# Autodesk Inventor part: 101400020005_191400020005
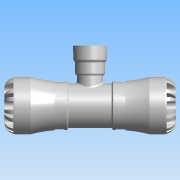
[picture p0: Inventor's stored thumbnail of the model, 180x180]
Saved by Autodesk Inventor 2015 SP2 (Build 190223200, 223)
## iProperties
Created: 2016-12
Part Number: 101400020005_191400020005
Material: PVC-Piping
Description: PLASSON TEE WITH THREADED FEMALE OFFTAKE 20X1/2" SERIES 1
Document SubType Name: Modeling
Designer: KIM
Mass: 664.223 g
Surface Area: 733.008 cm^2
Volume: 474.445 cm^3
Density: 1.4 g/cm^3
Appearance: Smooth - White
Author: KIM
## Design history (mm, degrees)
derived "1014.ipt"
feature "Solid1::1014.ipt"
tag "TaggingFeature1"
body "Solid1"
other parameters: "d1" = 18.9, "d3" = 25, "d4" = 41, "d8" = 34.85, "d13" = 6.4, "d14" = 6.4, "d15" = 0, "d17" = 360 deg, "d19" = 8 deg, "d20" = 0.4, "d21" = 0.4, "d22" = 8 deg, "d24" = 0, "d26" = 360 deg, "d33" = 4.1, "d43" = 31.98, "d51" = 0.41, "d54" = 7, "d55" = 4.4, "d57" = 12.544, "d58" = 0, "d74" = 0, "d77" = 1.66667, "d78" = 45, "d79" = 31.98, "d80" = 123, "d82" = 0.4, "d115" = 360 deg, "d139" = 6.4, "d140" = 0, "d142" = 360 deg, "d207" = 90 deg, "d228" = 5.95, "d247" = 0.82, "d248" = 2.7, "d266" = 0, "d268" = 18.631, "d270" = 2.79465, "d271" = 5.66667, "d274" = 1.39733, "d275" = 43, "d276" = 1.8631, "d277" = 1.8631, "d278" = 1.8631, "d279" = 1.8631, "d281" = 0, "d282" = 17, "E_" = 41, "l_" = 45, "A_" = 43, "H_" = 123, "Rp_" = 18.631, "l_2" = 17, "d9" = 8, "d11" = 41, "d12" = 25
